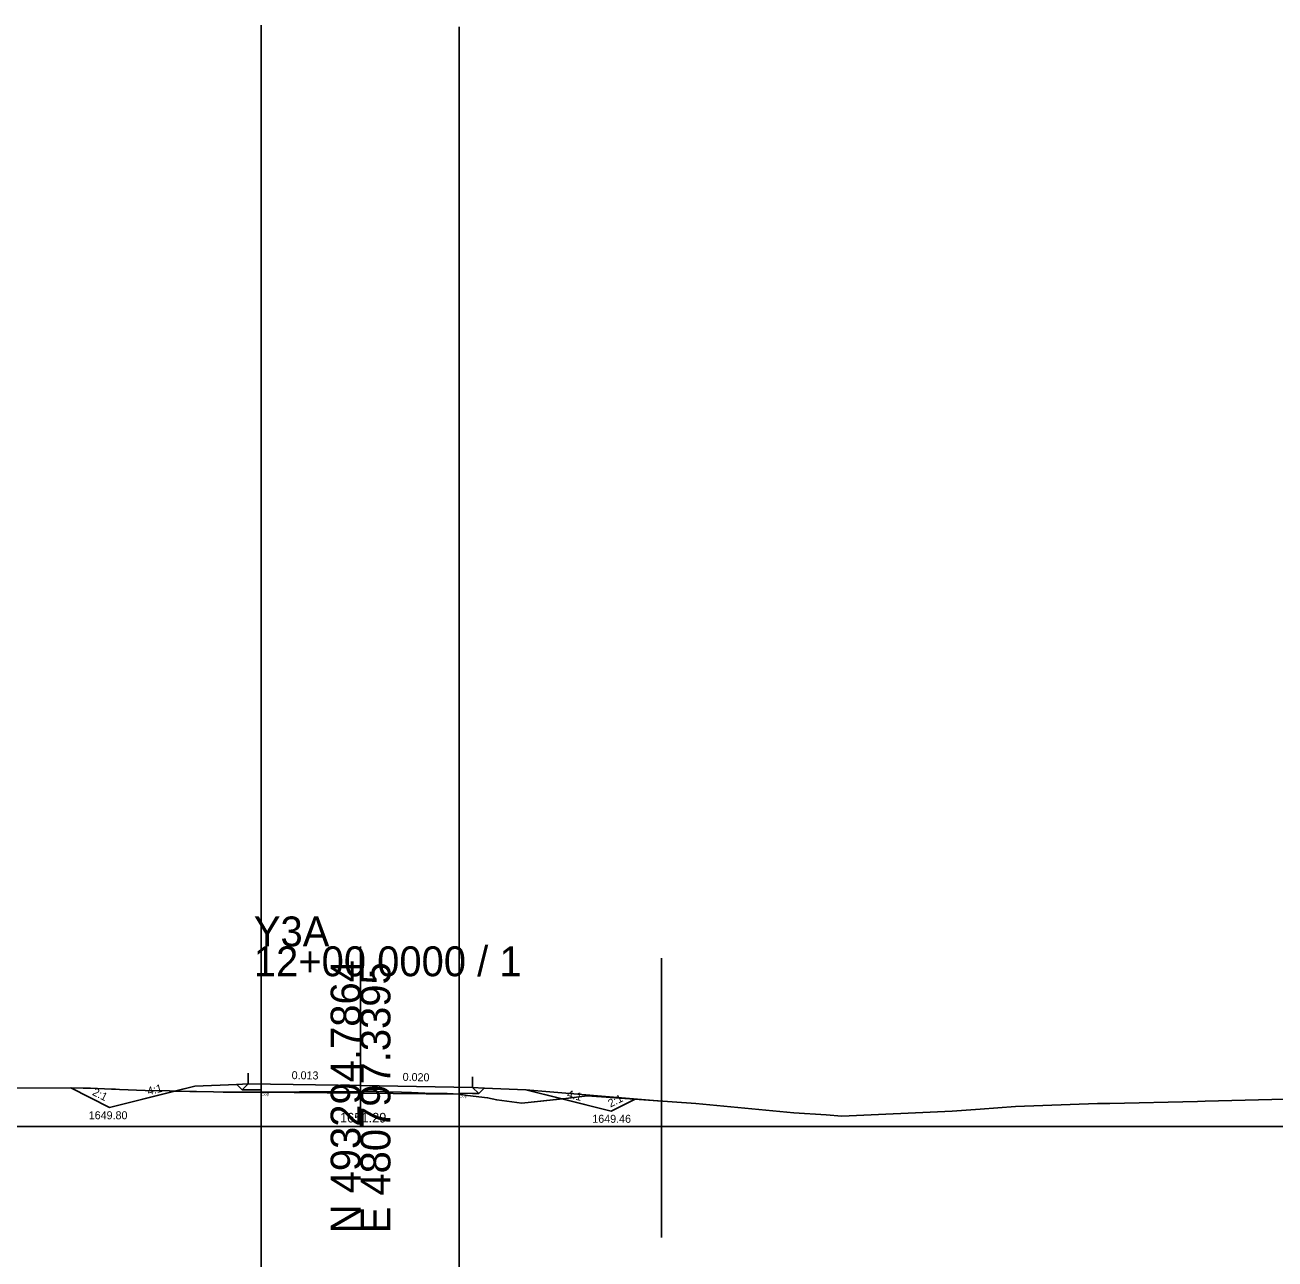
# Model space of a CAD drawing. Extents: x -26 to 403, y -10 to 3108.
# Drawn here: x 168.6 to 285.7, y 1987.6 to 2103.2 of the extents above; entities that cross this region are included whole.
import ezdxf

# ---------------------------------------------------------------- set-up
doc = ezdxf.new("R2010")
doc.units = 0
for name, color, linetype in [('Exist Cross Section Cell', 7, 'Continuous'), ('Exist XS Center Line Elevation Label', 7, 'Continuous'), ('Exist XS Ground Line', 7, 'Continuous'), ('Prop Road Sect_ Boring - Header (ID Tx)', 7, 'Continuous'), ('Prop Road Sect_ Material - Tx (Composite Desc)', 7, 'Continuous'), ('Prop XS Ditch Slope Text', 7, 'Continuous'), ('Prop XS Ditch Standard Text', 7, 'Continuous'), ('Prop XS Dump Level', 7, 'Continuous'), ('Prop XS Earthwork Shape', 7, 'Continuous'), ('Prop XS EOT Tick Mark', 7, 'Continuous'), ('Prop XS Finish Grade', 7, 'Continuous'), ('Prop XS Finish Grade Earthwork', 7, 'Continuous'), ('Prop XS Finish Grade Pavement', 7, 'Continuous'), ('Prop XS Hydro Typical Ditch Data', 7, 'Continuous'), ('Prop XS Pvmt Edge Slope', 7, 'Continuous'), ('Prop XS SE Text', 7, 'Continuous'), ('Prop XS Side Slope Text', 7, 'Continuous'), ('Prop XS Subgrade Earthwork', 7, 'Continuous'), ('Scratch_Level_1', 7, 'Continuous'), ('Scratch_Level_4', 7, 'Continuous')]:
    doc.layers.add(name, color=color, linetype=linetype)

msp = doc.modelspace()

# ---------------------------------------------------------------- linework, layer by layer
at = {"layer": 'Exist Cross Section Cell'}
for p, q in [((200, 2000), (200, 2016.89)), ((0, 2000), (200, 2000)), ((200, 2000), (400, 2000))]:
    msp.add_line(p, q, dxfattribs=at)
at = {"layer": 'Exist XS Ground Line'}
msp.add_lwpolyline([(167.48, 2003.65), (174.02, 2003.62), (174.7, 2003.59), (176.66, 2003.52), (177.05, 2003.5), (177.4, 2003.48), (179.82, 2003.4), (182.1, 2003.34), (184, 2003.29), (184.62, 2003.29), (186.21, 2003.26), (187.14, 2003.24), (188.41, 2003.24), (189.66, 2003.22), (190.13, 2003.22), (190.7, 2003.22), (192.19, 2003.24), (194.28, 2003.25), (194.72, 2003.25), (197.31, 2003.27), (200.03, 2003.29), (200.83, 2003.29), (201.54, 2003.28), (202.27, 2003.27), (203.85, 2003.22), (204.78, 2003.19), (206.04, 2003.15), (207.31, 2003.11), (208.13, 2003.09), (209.25, 2003.05), (210.03, 2002.92), (211.91, 2002.7), (212.76, 2002.51), (215.13, 2002.21), (219.24, 2002.65), (221.24, 2002.9), (231.42, 2002.17), (240.61, 2001.29), (243.64, 2001.12), (245.11, 2000.99), (255.43, 2001.46), (258.06, 2001.65), (261.38, 2001.88), (269.05, 2002.16), (270.22, 2002.16), (278.44, 2002.37), (279.15, 2002.39), (287.9, 2002.59)], dxfattribs=at)
at = {"layer": 'Prop Road Sect_ Boring - Header (ID Tx)'}
for points in [[(189.48, 2004), (188.4, 2003.96), (188.92, 2003.44)], [(210.5, 2003.66), (211.59, 2003.62), (211.07, 2003.1)]]:
    msp.add_lwpolyline(points, close=True, dxfattribs=at)
at = {"layer": 'Prop Road Sect_ Material - Tx (Composite Desc)'}
for points in [[(172.84, 2003.63), (174.02, 2003.62), (174.7, 2003.59), (176.66, 2003.52), (177.05, 2003.5), (177.4, 2003.48), (179.82, 2003.4), (182.1, 2003.34), (182.58, 2003.33), (176.48, 2001.8)], [(188.4, 2003.96), (188.92, 2003.44), (189.48, 2003.46), (190.7, 2003.45), (190.7, 2003.22), (190.13, 2003.22), (189.66, 2003.22), (188.41, 2003.24), (187.14, 2003.24), (186.21, 2003.26), (184.62, 2003.29), (184, 2003.29), (182.58, 2003.33), (184.48, 2003.8)], [(211.59, 2003.62), (215.5, 2003.46), (218.89, 2002.61), (215.13, 2002.21), (212.76, 2002.51), (211.91, 2002.7), (210.03, 2002.92), (209.25, 2003.05), (209.25, 2003.14), (210.5, 2003.12), (211.07, 2003.1)], [(221.24, 2002.9), (225.74, 2002.58), (223.5, 2001.46), (218.89, 2002.61), (219.24, 2002.65)]]:
    msp.add_lwpolyline(points, close=True, dxfattribs=at)
at = {"layer": 'Prop XS Dump Level'}
for p, q in [((189.48, 2004), (200, 2003.87)), ((200, 2003.87), (210.5, 2003.66))]:
    msp.add_line(p, q, dxfattribs=at)
at = {"layer": 'Prop XS Earthwork Shape'}
for points in [[(176.48, 2001.8), (172.84, 2003.63), (174.02, 2003.62), (174.7, 2003.59), (176.66, 2003.52), (177.05, 2003.5), (177.4, 2003.48), (179.82, 2003.4), (182.1, 2003.34), (182.58, 2003.33)], [(190.7, 2003.45), (189.48, 2003.46), (188.92, 2003.44), (188.4, 2003.96), (184.48, 2003.8), (182.58, 2003.33), (184, 2003.29), (184.62, 2003.29), (186.21, 2003.26), (187.14, 2003.24), (188.41, 2003.24), (189.66, 2003.22), (190.13, 2003.22), (190.7, 2003.22)], [(209.25, 2003.14), (210.5, 2003.12), (211.07, 2003.1), (211.59, 2003.62), (215.5, 2003.46), (218.89, 2002.61), (215.13, 2002.21), (212.76, 2002.51), (211.91, 2002.7), (210.03, 2002.92), (209.25, 2003.05)], [(223.5, 2001.46), (225.74, 2002.58), (221.24, 2002.9), (219.24, 2002.65), (218.89, 2002.61)]]:
    msp.add_lwpolyline(points, close=True, dxfattribs=at)
at = {"layer": 'Prop XS EOT Tick Mark'}
for p, q in [((189.48, 2004), (189.48, 2005)), ((210.5, 2003.66), (210.5, 2004.66))]:
    msp.add_line(p, q, dxfattribs=at)
at = {"layer": 'Prop XS Finish Grade'}
for p, q in [((189.48, 2004), (188.4, 2003.96)), ((210.5, 2003.66), (211.59, 2003.62))]:
    msp.add_line(p, q, dxfattribs=at)
at = {"layer": 'Prop XS Finish Grade Earthwork'}
for p, q in [((176.48, 2001.8), (172.84, 2003.63)), ((184.48, 2003.8), (176.48, 2001.8)), ((184.48, 2003.8), (188.4, 2003.96)), ((211.59, 2003.62), (215.5, 2003.46)), ((215.5, 2003.46), (223.5, 2001.46)), ((223.5, 2001.46), (225.74, 2002.58))]:
    msp.add_line(p, q, dxfattribs=at)
at = {"layer": 'Prop XS Finish Grade Pavement'}
for p, q in [((189.48, 2004), (200, 2003.87)), ((200, 2003.87), (210.5, 2003.66))]:
    msp.add_line(p, q, dxfattribs=at)
at = {"layer": 'Prop XS Hydro Typical Ditch Data'}
msp.add_line((176.48, 2001.8), (172.84, 2003.63), dxfattribs=at)
at = {"layer": 'Prop XS Pvmt Edge Slope'}
for p, q in [((189.48, 2004), (188.92, 2003.44)), ((210.5, 2003.66), (211.07, 2003.1))]:
    msp.add_line(p, q, dxfattribs=at)
at = {"layer": 'Prop XS Subgrade Earthwork'}
for p, q in [((188.4, 2003.96), (188.92, 2003.44)), ((189.48, 2003.46), (188.92, 2003.44)), ((190.7, 2003.45), (189.48, 2003.46)), ((190.7, 2003.45), (190.7, 2003.22)), ((209.25, 2003.14), (209.25, 2003.05)), ((209.25, 2003.14), (210.5, 2003.12)), ((211.59, 2003.62), (211.07, 2003.1)), ((210.5, 2003.12), (211.07, 2003.1))]:
    msp.add_line(p, q, dxfattribs=at)
at = {"layer": 'Scratch_Level_1'}
for p, q in [((190.7, 2103.22), (190.7, 1903.22)), ((209.25, 2103.05), (209.25, 1903.05))]:
    msp.add_line(p, q, dxfattribs=at)
at = {"layer": 'Scratch_Level_4'}
for p, q in [((228.21, 1989.6), (228.21, 2015.8)), ((190.7, 2003.22), (209.25, 2003.05)), ((215.5, 2003.46), (228.21, 2002.4))]:
    msp.add_line(p, q, dxfattribs=at)

# ---------------------------------------------------------------- texts
at = {"layer": 'Exist Cross Section Cell'}
for s, p in [('Y3A', (190, 2016.89)), ('12+00.0000 / 1', (190, 2014.09))]:
    msp.add_text(s, height=2.8, dxfattribs=at).set_placement(p)
for s, p in [('N 493294.7864', (200, 1990)), ('E 480797.3395', (202.8, 1990))]:
    msp.add_text(s, height=2.8, rotation=90, dxfattribs=at).set_placement(p)
at = {"layer": 'Exist XS Center Line Elevation Label'}
msp.add_text('1651.29', height=0.9, dxfattribs=at).set_placement((198.07, 2000.39))
at = {"layer": 'Prop XS Ditch Slope Text'}
for rotation, p in [(14.0362, (180.12, 2002.94)), (345.9638, (219.29, 2002.74))]:
    msp.add_text('4:1', height=0.75, rotation=rotation, dxfattribs=at).set_placement(p)
at = {"layer": 'Prop XS Ditch Standard Text'}
for s, p in [('1649.80', (174.53, 2000.69)), ('1649.46', (221.72, 2000.36))]:
    msp.add_text(s, height=0.75, dxfattribs=at).set_placement(p)
at = {"layer": 'Prop XS Dump Level'}
for s, height, p in [('Eop', 0.3, (190.7, 2002.92)), ('Case2', 0.04, (215.5, 2003.42)), ('Eop', 0.3, (209.25, 2002.75))]:
    msp.add_text(s, height=height, dxfattribs=at).set_placement(p)
at = {"layer": 'Prop XS SE Text'}
for s, rotation, p in [('0.013', 359.2743, (193.54, 2004.45)), ('0.020', 358.8542, (203.94, 2004.29))]:
    msp.add_text(s, height=0.75, rotation=rotation, dxfattribs=at).set_placement(p)
at = {"layer": 'Prop XS Side Slope Text'}
for rotation, p in [(333.4349, (174.8, 2003)), (26.5651, (223.42, 2001.78))]:
    msp.add_text('2:1', height=0.75, rotation=rotation, dxfattribs=at).set_placement(p)

doc.saveas('drawing.dxf')
